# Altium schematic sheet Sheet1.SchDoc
size A4; SheetNumber: 1; SheetTotal: 1
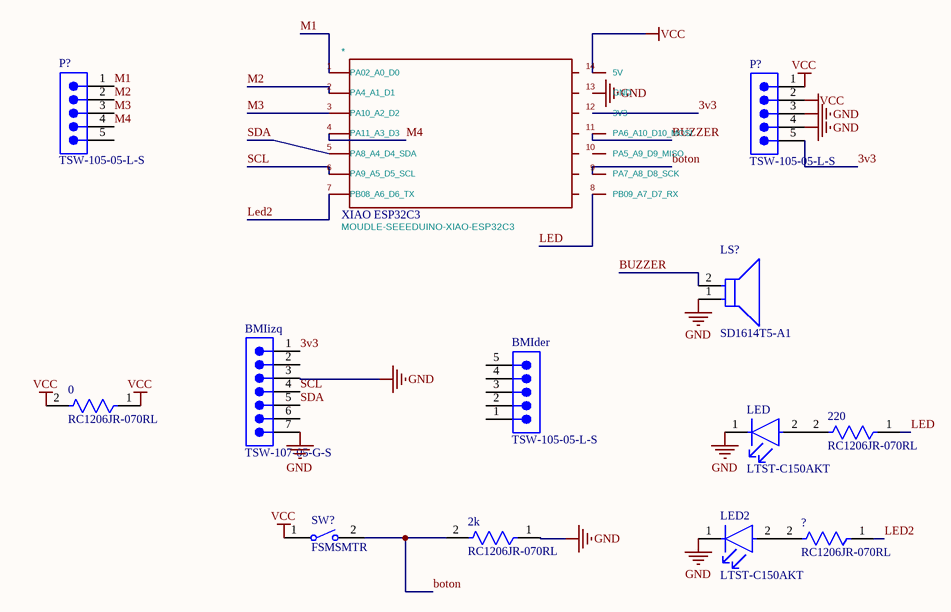
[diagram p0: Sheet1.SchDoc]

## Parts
(Parts that share a designator on the sheet are numbered #1, #2 ... from top to bottom, then left to right.)
0  RC1206JR-070RL  [FP-RC1206-MFG]
2k  RC1206JR-070RL  [FP-RC1206-MFG]
220  RC1206JR-070RL  [FP-RC1206-MFG]
*  XIAO ESP32C3  value MOUDLE-SEEEDUINO-XIAO-ESP32C3  [MOUDLE14P-SMD-2.54-21X17.8MM]
?  RC1206JR-070RL  [FP-RC1206-MFG]
BMIder  TSW-105-05-L-S  [SMTC-TSW-105-05-X-S]
BMIizq  TSW-107-05-G-S  [SMTC-TSW-107-05-X-S]
LED  LTST-C150AKT  [FP-LTST-C150AKT-MFG]
LED2  LTST-C150AKT  [FP-LTST-C150AKT-MFG]
LS?  SD1614T5-A1  [FP-SD1614T5-A1-MFG]
P?#1  TSW-105-05-L-S  [SMTC-TSW-105-05-X-S]
P?#2  TSW-105-05-L-S  [SMTC-TSW-105-05-X-S]
SW?  FSMSMTR  [TECO-FSMSMTR_V]

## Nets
GND: 2k.1 *.13(GND) BMIizq.3 BMIizq.7 LED.1(C) LED2.1(C) LS?.1(C) P?#2.3 P?#2.4
VCC: 0.1 0.2 *.14(5V) P?#2.1 P?#2.2 SW?.1
3v3: *.12(3V3) BMIizq.1 P?#2.5
boton: 2k.2 *.9(PA7_A8_D8_SCK) SW?.2
BUZZER: *.11(PA6_A10_D10_MOSI) LS?.2(A)
LED: 220.1 *.8(PB09_A7_D7_RX)
LED2: *.7(PB08_A6_D6_TX) ?.1
M1: *.1(PA02_A0_D0) P?#1.1
M2: *.2(PA4_A1_D1) P?#1.2
M3: *.3(PA10_A2_D2) P?#1.3
M4: *.4(PA11_A3_D3) P?#1.4
SCL: *.6(PA9_A5_D5_SCL) BMIizq.4
SDA: *.5(PA8_A4_D4_SDA) BMIizq.5
Net220_2: 220.2 LED.2(A)
Net?_2: ?.2 LED2.2(A)

Not connected (* = marked no-connect by the designer): * 10(PA5_A9_D9_MISO); BMIder 1 2 3 4 5; BMIizq 2 6; P?#1 5

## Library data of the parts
0 2k 220 ? = CMP-2100-03681-2: RES SMD 0 OHM JUMPER 1/4W 1206; Manufacturer: YAGEO; Voltage Rating: 200V; Temperature Coefficient: 300ppm/°C; Power Rating: 0.25W; Value: 0Ω; Tolerance: 5%
* = MOUDLE-SEEEDUINO-XIAO-ESP32C3
BMIder P?#1 P?#2 = CMP-1024-00366-1: 0.025" SQ Post Header, Through-hole, Vertical, -55 to 125 degC, 2.54 mm Pitch, 5-Pin, Male, RoHS; Manufacturer: Samtec; Pitch: 2.54 mm
BMIizq = CMP-1024-00400-1: 0.025" SQ Post Header, Through-hole, Vertical, -55 to 125 degC, 2.54 mm Pitch, 7-Pin, Male, RoHS; Manufacturer: Samtec; Pitch: 2.54 mm
LED LED2 = CMP-22017-000004-1: LED AMBER CLEAR SMD; Manufacturer: Lite-On; Luminous Intensity: 6mcd; Viewing Angle: 130°; Wavelength: 602nm; Reverse Voltage: 5V; Forward Current: 30mA; Led Orientation: Top View; Power Dissipation: 100mW; Peak Emmision Wavelength: 610nm; Forward Voltage: 2.1V
LS? = CMP-08413-000005-1: BUZZER MAGNETIC 5V 80DB 2048HZ 1; Frequency: 2.048kHz; Operating Supply Current: 80mA
SW? = CMP-2000-07501-1: FSMSM Push Button Switch, 50 mA, -35 to 85 degC, 2-Pin SMD, RoHS, Tape and Reel; Manufacturer: TE Connectivity; Voltage Rating (DC): 24V; Electrical Life: 20000Cycles; Operating Force: 180gf; Switch Travel: 0.25mm; Contact Current Rating: 50mA; Case\/Package: SMD/SMT; Actuator Length: 1.07mm; Throw Configuration: SPST; Actuator Material: Polyamide; Contact Resistance: 100mOhm; Illumination Type: Illuminated; Max Voltage Rating (DC): 12V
